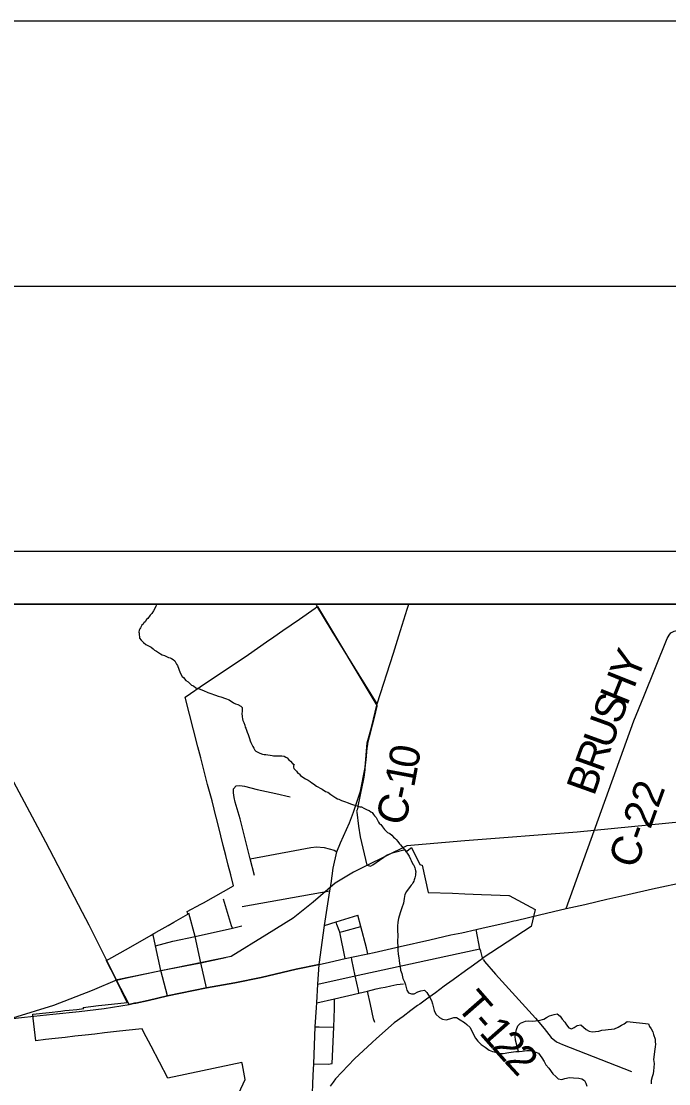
# Model space of a CAD drawing. Extents: x 0 to 34, y 0 to 22.
# Drawn here: x 7.241 to 8.463, y 19.995 to 22 of the extents above; entities that cross this region are included whole.
import ezdxf

# ---------------------------------------------------------------- set-up
doc = ezdxf.new("R2010")
doc.units = 0
for name, color, linetype in [('GM_X_City_Street', 7, 'Continuous'), ('GM_X_Corporation', 7, 'Continuous'), ('GM_X_County_Road', 7, 'Continuous'), ('GM_X_County_Road_Text', 7, 'Continuous'), ('GM_X_Minor_River', 7, 'Continuous'), ('GM_X_Rail_Line', 7, 'Continuous'), ('GM_X_State_Route', 7, 'Continuous'), ('GM_X_Township_Road', 7, 'Continuous'), ('GM_X_Township_Road_Text', 7, 'Continuous'), ('GM_X_US_Route', 7, 'Continuous'), ('SH_Border', 7, 'Continuous'), ('SH_Cut_Line', 7, 'Continuous'), ('SH_Data', 7, 'Continuous')]:
    doc.layers.add(name, color=color, linetype=linetype)

msp = doc.modelspace()

# ---------------------------------------------------------------- linework, layer by layer
at = {"layer": 'GM_X_City_Street'}
msp.add_line((7.6574, 20.3301), (7.823, 20.3596), dxfattribs=at)
for points in [[(7.6809, 20.3883), (7.6729, 20.4199), (7.6539, 20.4951), (7.6446, 20.5269), (7.6423, 20.5353), (7.6409, 20.5442), (7.6413, 20.5521), (7.6461, 20.5573), (7.6532, 20.5581), (7.6619, 20.5566), (7.6861, 20.5507), (7.7208, 20.5429), (7.7483, 20.5366)], [(7.8027, 20.2202), (7.8131, 20.2941), (7.823, 20.3596), (7.8252, 20.3734), (7.8296, 20.4023), (7.8364, 20.4327), (7.8431, 20.45), (7.8599, 20.4875), (7.8677, 20.5081)], [(7.6729, 20.4199), (7.7572, 20.4353), (7.7874, 20.4412), (7.7976, 20.4422), (7.8124, 20.441), (7.8312, 20.4363), (7.8364, 20.4327)], [(7.6394, 20.2892), (7.6377, 20.2935), (7.6221, 20.344)], [(7.5903, 20.1767), (7.5795, 20.2234), (7.5686, 20.2732), (7.5569, 20.3175)], [(7.8131, 20.2941), (7.835, 20.3011), (7.8757, 20.3133)], [(7.8949, 20.2406), (7.8923, 20.2521), (7.8816, 20.2923), (7.8757, 20.3133)], [(7.494, 20.2555), (7.5269, 20.2647), (7.5686, 20.2732), (7.6394, 20.2892), (7.6566, 20.2936)], [(7.8522, 20.2316), (7.842, 20.2815), (7.8365, 20.2961), (7.835, 20.3011)], [(7.842, 20.2815), (7.8497, 20.2831), (7.8816, 20.2923)], [(8.1133, 20.2293), (8.1114, 20.2331), (8.1096, 20.238), (8.1079, 20.2457), (8.1064, 20.2502), (8.099, 20.2864)], [(7.5168, 20.161), (7.5043, 20.2091), (7.494, 20.2555), (7.4895, 20.2767)], [(7.8004, 20.1832), (7.8711, 20.1989), (8.042, 20.2362), (8.1064, 20.2502)], [(7.4206, 20.1906), (7.4391, 20.1952), (7.5043, 20.2091), (7.5795, 20.2234), (7.626, 20.2334)], [(7.8711, 20.1989), (7.8648, 20.2291), (7.8641, 20.2344)], [(7.8779, 20.1662), (7.8772, 20.1716), (7.8711, 20.1989)], [(7.7984, 20.1484), (7.8319, 20.1558), (7.8779, 20.1662), (7.894, 20.17), (7.9105, 20.1743), (7.9191, 20.1761)], [(7.9078, 20.1109), (7.9057, 20.1182), (7.8998, 20.1448), (7.894, 20.17)], [(7.9191, 20.1761), (7.9276, 20.1779), (7.9382, 20.18), (7.9493, 20.1825), (7.9619, 20.1841)], [(7.8276, 20.0334), (7.8308, 20.102), (7.8318, 20.1375), (7.8319, 20.1558)], [(7.7952, 20.1028), (7.8031, 20.1027), (7.8308, 20.102)], [(7.793, 20.0332), (7.8198, 20.0322), (7.8276, 20.0334)]]:
    msp.add_lwpolyline(points, dxfattribs=at)
at = {"layer": 'GM_X_Corporation'}
for points in [[(8.9, 18.9286), (8.9, 20.9), (3.0971, 20.9)], [(7.6513, 19.9777), (7.6633, 20.0035), (7.658, 20.0314), (7.6571, 20.0357), (7.5828, 20.0199), (7.5175, 20.006), (7.4858, 20.0663), (7.4716, 20.0933), (7.4685, 20.0993), (7.4624, 20.0986), (7.426, 20.0945), (7.3977, 20.0913), (7.3792, 20.0892), (7.361, 20.0872), (7.342, 20.085), (7.3233, 20.0829), (7.3047, 20.0808), (7.2861, 20.0787), (7.2679, 20.0767), (7.2633, 20.1189), (7.2627, 20.1266), (7.2934, 20.1301), (7.3151, 20.1325), (7.3231, 20.1334), (7.3307, 20.1343), (7.3454, 20.1358), (7.3585, 20.1372), (7.3573, 20.1395), (7.3863, 20.1428), (7.3987, 20.1446), (7.4406, 20.149), (7.4188, 20.1929), (7.4104, 20.2106), (7.4013, 20.2276), (7.401, 20.2282), (7.4057, 20.2307), (7.4429, 20.2515), (7.4858, 20.276), (7.491, 20.2789), (7.4944, 20.2809), (7.4953, 20.2814), (7.5176, 20.2943), (7.5283, 20.3004), (7.5549, 20.3154), (7.5538, 20.3203), (7.5796, 20.3343), (7.5846, 20.3369), (7.6412, 20.3687), (7.6359, 20.3896), (7.6312, 20.4081), (7.6266, 20.4263), (7.6218, 20.4452), (7.6173, 20.4631), (7.6089, 20.4963), (7.6086, 20.4977), (7.6006, 20.5291), (7.5922, 20.5599), (7.5793, 20.6104), (7.5739, 20.6311), (7.5499, 20.7248), (7.5882, 20.7511), (7.6443, 20.7883), (7.6692, 20.8055), (7.7034, 20.8291), (7.7172, 20.8387), (7.734, 20.8503), (7.7656, 20.8722), (7.7954, 20.8928), (7.7956, 20.8929), (7.7987, 20.895), (7.7997, 20.8957), (7.912, 20.7088), (7.9119, 20.7084), (7.9118, 20.7082), (7.9118, 20.7079), (7.9117, 20.7076), (7.9117, 20.7075), (7.9116, 20.707), (7.9115, 20.707), (7.9114, 20.7065), (7.9114, 20.7064), (7.9113, 20.706), (7.9113, 20.7058), (7.9112, 20.7055), (7.9111, 20.7052), (7.9111, 20.705), (7.911, 20.7046), (7.9109, 20.7045), (7.9108, 20.704), (7.9107, 20.7036), (7.9107, 20.7034), (7.9106, 20.7031), (7.9105, 20.7028), (7.9105, 20.7026), (7.9104, 20.7022), (7.9103, 20.7021), (7.9102, 20.7016), (7.9102, 20.7016), (7.9101, 20.7011), (7.9101, 20.701), (7.91, 20.7006), (7.9099, 20.7004), (7.9099, 20.7002), (7.9098, 20.6998), (7.9097, 20.6997), (7.9096, 20.6992), (7.9095, 20.6987), (7.9094, 20.6982), (7.9094, 20.6981), (7.9093, 20.6977), (7.9092, 20.6975), (7.9092, 20.6972), (7.909, 20.6967), (7.9089, 20.6963), (7.9028, 20.6722), (7.8995, 20.6593), (7.8944, 20.6377), (7.8944, 20.6374), (7.8943, 20.6372), (7.8943, 20.637), (7.8943, 20.6367), (7.8942, 20.6365), (7.8942, 20.6362), (7.8941, 20.636), (7.8941, 20.6358), (7.894, 20.6355), (7.894, 20.6353), (7.8939, 20.635), (7.8939, 20.6348), (7.8939, 20.6346), (7.8938, 20.6343), (7.8938, 20.6341), (7.8937, 20.6338), (7.8937, 20.6336), (7.8936, 20.6333), (7.8936, 20.6331), (7.8936, 20.6329), (7.8935, 20.6326), (7.8935, 20.6324), (7.8934, 20.6321), (7.8934, 20.6319), (7.8934, 20.6317), (7.8933, 20.6314), (7.8933, 20.6312), (7.8933, 20.6309), (7.8932, 20.6307), (7.8932, 20.6304), (7.8932, 20.6302), (7.8931, 20.63), (7.8931, 20.6297), (7.8931, 20.6295), (7.893, 20.6292), (7.893, 20.629), (7.893, 20.6287), (7.8929, 20.6285), (7.8929, 20.6283), (7.8929, 20.628), (7.8928, 20.6278), (7.8928, 20.6275), (7.8928, 20.6273), (7.8928, 20.627), (7.8927, 20.6268), (7.8927, 20.6266), (7.8927, 20.6263), (7.8926, 20.6261), (7.8926, 20.6258), (7.8926, 20.6256), (7.8926, 20.6253), (7.8925, 20.6251), (7.8925, 20.6248), (7.8925, 20.6246), (7.8925, 20.6244), (7.8924, 20.6241), (7.8924, 20.6239), (7.8924, 20.6236), (7.8924, 20.6234), (7.8924, 20.6231), (7.8923, 20.6229), (7.8922, 20.6215), (7.8914, 20.6126), (7.8893, 20.5907), (7.8893, 20.5903), (7.8892, 20.5899), (7.8892, 20.5895), (7.8892, 20.5891), (7.8891, 20.5887), (7.8891, 20.5883), (7.889, 20.5879), (7.889, 20.5875), (7.8889, 20.5871), (7.8889, 20.5868), (7.8889, 20.5864), (7.8888, 20.586), (7.8888, 20.5856), (7.8887, 20.5852), (7.8887, 20.5848), (7.8886, 20.5844), (7.8886, 20.584), (7.8885, 20.5836), (7.8885, 20.5832), (7.8884, 20.5828), (7.8884, 20.5824), (7.8883, 20.582), (7.8883, 20.5816), (7.8882, 20.5812), (7.8881, 20.5808), (7.8881, 20.5804), (7.888, 20.58), (7.888, 20.5796), (7.8879, 20.5792), (7.8879, 20.5788), (7.8878, 20.5784), (7.8877, 20.578), (7.8877, 20.5776), (7.8876, 20.5772), (7.8876, 20.5768), (7.8875, 20.5764), (7.8874, 20.576), (7.8874, 20.5756), (7.8873, 20.5752), (7.8872, 20.5748), (7.8872, 20.5744), (7.8871, 20.574), (7.887, 20.5736), (7.887, 20.5733), (7.8869, 20.5729), (7.8868, 20.5725), (7.8868, 20.5721), (7.8867, 20.5717), (7.8866, 20.5713), (7.8865, 20.5709), (7.8865, 20.5705), (7.8864, 20.5701), (7.8863, 20.5697), (7.8862, 20.5693), (7.8862, 20.5689), (7.8861, 20.5685), (7.886, 20.5681), (7.8859, 20.5677), (7.8858, 20.5673), (7.8858, 20.5669), (7.8857, 20.5666), (7.8856, 20.5662), (7.8855, 20.5658), (7.8854, 20.5654), (7.8854, 20.565), (7.8853, 20.5646), (7.8852, 20.5642), (7.8851, 20.5638), (7.885, 20.5634), (7.8849, 20.563), (7.8848, 20.5626), (7.8848, 20.5622), (7.8847, 20.5618), (7.8846, 20.5615), (7.8845, 20.5611), (7.8844, 20.5607), (7.8843, 20.5603), (7.8842, 20.5599), (7.8841, 20.5595), (7.884, 20.5591), (7.8839, 20.5587), (7.8761, 20.5194), (7.8757, 20.5174), (7.8749, 20.5122), (7.8735, 20.5094), (7.8737, 20.5078), (7.8774, 20.4813), (7.8801, 20.4611), (7.8931, 20.4078), (7.8932, 20.4078), (7.9, 20.4058), (7.904, 20.4085), (7.9314, 20.4272), (7.9318, 20.4274), (7.9425, 20.4316), (7.9433, 20.4318), (7.965, 20.4376), (7.9666, 20.4329), (7.9774, 20.4409), (7.9928, 20.4093), (7.9968, 20.4079), (7.9971, 20.4078), (8.0085, 20.3563), (8.0548, 20.3547), (8.0775, 20.3538), (8.1093, 20.3527), (8.1278, 20.3521), (8.1444, 20.3515), (8.1611, 20.3508), (8.1613, 20.3508), (8.2108, 20.3239), (8.2029, 20.2922), (8.1125, 20.2328), (8.1102, 20.2311), (8.1081, 20.2295), (8.0896, 20.2161), (8.0834, 20.2116), (8.072, 20.2033), (8.0652, 20.1984), (8.0557, 20.1914), (8.0433, 20.1824), (8.039, 20.1793), (8.0222, 20.1671), (8.0056, 20.155), (7.9931, 20.1459), (7.9887, 20.1428), (7.976, 20.1336), (7.9611, 20.1224), (7.9443, 20.1101), (7.9112, 20.081), (7.9029, 20.0733), (7.8694, 20.0422), (7.8338, 20.0045), (7.8293, 19.9984), (7.8236, 19.9907)]]:
    msp.add_lwpolyline(points, dxfattribs=at)
at = {"layer": 'GM_X_County_Road'}
for points in [[(7.9121, 20.7122), (7.9433, 20.8079), (7.9531, 20.8407), (7.9688, 20.8907), (7.972, 20.9)], [(8.269, 20.3262), (8.3971, 20.68), (8.4155, 20.7258), (8.4599, 20.8356), (8.4634, 20.8415), (8.4669, 20.846), (8.4731, 20.8493), (8.4837, 20.8517), (8.4996, 20.8521), (8.5272, 20.8519), (8.5461, 20.8511), (8.5563, 20.8517), (8.5643, 20.8526), (8.5738, 20.8566), (8.583, 20.8632), (8.5919, 20.8687), (8.6071, 20.8752), (8.6469, 20.8937), (8.6571, 20.9)], [(7.8677, 20.5081), (7.8808, 20.5476), (7.8894, 20.5919), (7.8937, 20.6386), (7.9017, 20.6676), (7.9121, 20.7122)]]:
    msp.add_lwpolyline(points, dxfattribs=at)
at = {"layer": 'GM_X_Minor_River'}
for points in [[(7.4969, 20.9), (7.4952, 20.8981), (7.4948, 20.8958), (7.49, 20.8876), (7.4872, 20.8827), (7.4841, 20.8798), (7.4794, 20.8734), (7.4767, 20.8712), (7.4743, 20.8671), (7.472, 20.8649), (7.4704, 20.8627), (7.4684, 20.8604), (7.4672, 20.8582), (7.4657, 20.8556), (7.4641, 20.8534), (7.4633, 20.8511), (7.4628, 20.8477), (7.4631, 20.8454), (7.4634, 20.8416), (7.4637, 20.8393), (7.464, 20.8363), (7.4666, 20.8324), (7.471, 20.8278), (7.4755, 20.8242), (7.4785, 20.823), (7.4819, 20.821), (7.4856, 20.819), (7.4897, 20.8159), (7.4923, 20.8135), (7.4961, 20.8115), (7.5031, 20.8064), (7.5065, 20.8044), (7.5107, 20.8032), (7.5186, 20.7999), (7.5216, 20.7987), (7.5242, 20.7979), (7.5276, 20.7959), (7.5302, 20.7932), (7.5338, 20.787), (7.5356, 20.7843), (7.5406, 20.7709), (7.5442, 20.764), (7.5468, 20.762), (7.5512, 20.7562), (7.5557, 20.7538), (7.5617, 20.7476), (7.5658, 20.746), (7.5699, 20.7425), (7.5763, 20.7404), (7.5846, 20.7375), (7.5928, 20.7339), (7.5966, 20.7323), (7.6075, 20.7286), (7.6124, 20.7269), (7.6173, 20.7257), (7.6263, 20.722), (7.6331, 20.7199), (7.6413, 20.7144), (7.6451, 20.7124), (7.6492, 20.7108)], [(7.6492, 20.7108), (7.6552, 20.7076), (7.6574, 20.7053), (7.6576, 20.6969), (7.6572, 20.6946), (7.6574, 20.6874), (7.6584, 20.6836), (7.6587, 20.6809), (7.6605, 20.6767), (7.6627, 20.6717), (7.6633, 20.6683), (7.6644, 20.666), (7.6669, 20.6587), (7.6691, 20.6545), (7.6694, 20.6522), (7.6715, 20.6465), (7.6726, 20.6426), (7.674, 20.6392), (7.6776, 20.6319), (7.6798, 20.6288), (7.6816, 20.6249), (7.6834, 20.6226), (7.6906, 20.619), (7.6958, 20.6174), (7.6989, 20.6169), (7.7023, 20.6164), (7.7061, 20.616), (7.7106, 20.6151), (7.7144, 20.6146), (7.7167, 20.6142), (7.7193, 20.6141), (7.7227, 20.6144), (7.7326, 20.6141), (7.7371, 20.6133), (7.7401, 20.6117), (7.7424, 20.6101), (7.7457, 20.6066), (7.7487, 20.6038), (7.7524, 20.5996), (7.7554, 20.5976), (7.7545, 20.595), (7.7545, 20.5927), (7.7552, 20.59), (7.7574, 20.5877), (7.76, 20.5853), (7.7625, 20.5815), (7.7648, 20.5803), (7.7677, 20.5768), (7.7719, 20.574), (7.7771, 20.5705), (7.7823, 20.5684), (7.7861, 20.5657), (7.789, 20.5629), (7.7924, 20.5613), (7.798, 20.557), (7.8003, 20.5558), (7.8047, 20.5531), (7.8085, 20.5514), (7.8148, 20.5471), (7.819, 20.5455), (7.8246, 20.5412), (7.8287, 20.5384), (7.8343, 20.5348), (7.8373, 20.5332), (7.8399, 20.5324), (7.8452, 20.5296), (7.8508, 20.5279), (7.8576, 20.5255), (7.8617, 20.5235), (7.8659, 20.5226), (7.8719, 20.5206), (7.8749, 20.5197), (7.8798, 20.5181), (7.8825, 20.5176), (7.887, 20.5156), (7.89, 20.5144), (7.8937, 20.5124), (7.8975, 20.5108), (7.9001, 20.5084), (7.9027, 20.5069), (7.9057, 20.5037), (7.9071, 20.5007), (7.9104, 20.4979), (7.9148, 20.4891), (7.917, 20.486), (7.9192, 20.4844), (7.9222, 20.4802), (7.924, 20.4775), (7.9262, 20.4751), (7.9321, 20.4697), (7.9363, 20.4673), (7.94, 20.4645), (7.9429, 20.4607), (7.9459, 20.4587), (7.9481, 20.4563), (7.9511, 20.4525), (7.9548, 20.4482), (7.9566, 20.4459), (7.9588, 20.4432), (7.9658, 20.4346), (7.9702, 20.4284)], [(7.9702, 20.4284), (7.9728, 20.4246), (7.9753, 20.4192), (7.9764, 20.4165), (7.9796, 20.41), (7.9815, 20.4077), (7.9832, 20.4031), (7.9843, 20.4004), (7.985, 20.3973), (7.9853, 20.395), (7.9849, 20.3924), (7.9848, 20.389), (7.9843, 20.3867), (7.9835, 20.3837), (7.9823, 20.3803), (7.9815, 20.3777), (7.9795, 20.3747), (7.9783, 20.3721), (7.9767, 20.3699), (7.9747, 20.3676)], [(7.9747, 20.3676), (7.9674, 20.3584), (7.9646, 20.3523), (7.9633, 20.3451), (7.962, 20.336), (7.9588, 20.3273), (7.9556, 20.3179), (7.9524, 20.3069), (7.9512, 20.3001), (7.9507, 20.2925), (7.9505, 20.2849), (7.9511, 20.2746), (7.9509, 20.2643), (7.9511, 20.2525), (7.9514, 20.2476), (7.952, 20.24), (7.9531, 20.2331), (7.9537, 20.2278), (7.9548, 20.2224), (7.9555, 20.2167), (7.9561, 20.2098), (7.9587, 20.2037), (7.9608, 20.1942), (7.9641, 20.1876), (7.9659, 20.1819), (7.9684, 20.1723), (7.9717, 20.167), (7.9774, 20.1653), (7.9823, 20.1649), (7.9892, 20.1689), (7.9946, 20.1707), (8.0015, 20.1718), (8.0063, 20.1679), (8.0111, 20.1594), (8.0148, 20.1525), (8.0166, 20.1464), (8.0184, 20.1384), (8.0198, 20.1334), (8.0231, 20.1269), (8.0302, 20.1203), (8.0359, 20.1175), (8.0423, 20.1159), (8.0492, 20.1181), (8.0569, 20.1206), (8.0622, 20.1205), (8.0693, 20.1158), (8.0769, 20.1111), (8.0817, 20.1072), (8.0877, 20.1018), (8.0929, 20.091), (8.098, 20.0814), (8.1025, 20.076), (8.1088, 20.0695), (8.116, 20.0644), (8.1239, 20.0586), (8.1303, 20.0562), (8.136, 20.0549), (8.1428, 20.0525), (8.15, 20.0524), (8.1607, 20.0545), (8.174, 20.0562), (8.1805, 20.0564), (8.1858, 20.0571), (8.195, 20.0581), (8.1999, 20.058), (8.2048, 20.0575), (8.2101, 20.0555), (8.2169, 20.0531), (8.2232, 20.0446), (8.2273, 20.0377), (8.231, 20.0312), (8.2362, 20.0246), (8.2436, 20.0139), (8.2493, 20.0092), (8.2541, 20.0049), (8.2606, 20.0033), (8.2663, 20.0055), (8.2751, 20.0072), (8.2831, 20.0067), (8.2929, 20.0058), (8.2986, 20.0045), (8.3039, 20.0014), (8.3061, 19.9964), (8.3079, 19.991)], [(8.1789, 20.0564), (8.1732, 20.0775), (8.1726, 20.0851), (8.1739, 20.0919), (8.1755, 20.0976), (8.1779, 20.1048), (8.1829, 20.1096), (8.1921, 20.1133), (8.1986, 20.1139), (8.2058, 20.1138), (8.2115, 20.1141), (8.2172, 20.1147), (8.2271, 20.1172), (8.2321, 20.1202), (8.2375, 20.1235), (8.2463, 20.1264), (8.252, 20.1271), (8.2576, 20.1232), (8.2613, 20.1174), (8.2666, 20.1116), (8.2699, 20.1066), (8.2744, 20.1012), (8.2793, 20.0992), (8.2843, 20.1018), (8.29, 20.1055), (8.2969, 20.1069), (8.3018, 20.1022), (8.307, 20.0976), (8.3127, 20.0944), (8.318, 20.0936), (8.3244, 20.0938), (8.3305, 20.0949), (8.3363, 20.0963), (8.3431, 20.0969), (8.3485, 20.0976), (8.3549, 20.0982), (8.3606, 20.0989), (8.3675, 20.1022), (8.3733, 20.1059), (8.3783, 20.1085), (8.3841, 20.1126)], [(8.3841, 20.1126), (8.4244, 20.1083), (8.4266, 20.1037), (8.4295, 20.099), (8.4328, 20.0936), (8.4342, 20.0886), (8.437, 20.0794), (8.4372, 20.0744), (8.4375, 20.0699), (8.4373, 20.0653), (8.4359, 20.0562), (8.435, 20.0505), (8.434, 20.0414), (8.4349, 20.0338), (8.4347, 20.0258), (8.4342, 20.0201), (8.4332, 20.0144), (8.4316, 20.0083), (8.4298, 20.0015), (8.4297, 19.9951)]]:
    msp.add_lwpolyline(points, dxfattribs=at)
at = {"layer": 'GM_X_Rail_Line'}
msp.add_lwpolyline([(8.9, 20.5317), (8.865, 20.5331), (8.6616, 20.5066), (8.2899, 20.47), (8.0777, 20.4538), (7.9686, 20.4444), (7.8915, 20.4068), (7.8679, 20.3946), (7.8333, 20.3737), (7.7918, 20.3381), (7.7538, 20.3081), (7.7039, 20.2773), (7.6367, 20.2356), (7.4218, 20.1917), (7.3745, 20.1714), (7.3015, 20.143), (7.2242, 20.1194), (6.8196, 20.081), (6.5058, 20.0545), (6.3266, 19.9988), (6.3068, 19.9813)], dxfattribs=at)
at = {"layer": 'GM_X_State_Route'}
for p, q in [((7.8004, 20.1832), (7.8027, 20.2202)), ((7.5903, 20.1767), (7.5168, 20.161)), ((7.7984, 20.1484), (7.8004, 20.1832)), ((7.4545, 20.1472), (7.4442, 20.1448)), ((7.7978, 20.1393), (7.7984, 20.1484)), ((7.7952, 20.1028), (7.7978, 20.1393)), ((7.793, 20.0332), (7.7952, 20.1028))]:
    msp.add_line(p, q, dxfattribs=at)
for points in [[(7.3563, 20.3183), (7.2869, 20.4512), (7.2163, 20.5836), (7.1774, 20.6568), (7.1438, 20.7179), (7.1209, 20.7646), (7.0934, 20.8162), (7.0666, 20.8644), (7.0484, 20.9)], [(7.4442, 20.1448), (7.4206, 20.1906), (7.4025, 20.2269), (7.3687, 20.2945), (7.3563, 20.3183)], [(7.8027, 20.2202), (7.7596, 20.2117), (7.6932, 20.1961), (7.6439, 20.1861), (7.5903, 20.1767)], [(7.5168, 20.161), (7.4803, 20.1524), (7.4566, 20.1477), (7.4545, 20.1472)], [(7.7882, 19.9307), (7.7884, 19.938), (7.7894, 19.9612), (7.7917, 20.0117), (7.793, 20.0332)]]:
    msp.add_lwpolyline(points, dxfattribs=at)
at = {"layer": 'GM_X_Township_Road'}
for points in [[(7.9121, 20.7122), (7.8784, 20.7669), (7.8273, 20.8496), (7.7986, 20.8973), (7.7971, 20.9)], [(8.1133, 20.2293), (8.115, 20.2261), (8.1355, 20.2025), (8.2115, 20.1191), (8.2275, 20.0994), (8.2409, 20.083), (8.2508, 20.0744), (8.2622, 20.0693), (8.3926, 20.0184)]]:
    msp.add_lwpolyline(points, dxfattribs=at)
at = {"layer": 'GM_X_US_Route'}
for p, q in [((7.5168, 20.161), (7.5903, 20.1767)), ((7.4442, 20.1448), (7.4545, 20.1472))]:
    msp.add_line(p, q, dxfattribs=at)
for points in [[(8.3276, 20.3392), (8.3459, 20.3436), (8.3856, 20.3526), (8.4323, 20.3633), (8.4969, 20.3771), (8.5599, 20.3919), (8.6133, 20.4038), (8.6745, 20.4178), (8.7359, 20.4325), (8.8125, 20.4497), (8.8623, 20.461), (8.9, 20.4695)], [(8.2452, 20.3204), (8.269, 20.3262), (8.3045, 20.3336), (8.3276, 20.3392)], [(8.1749, 20.3036), (8.2186, 20.314), (8.2452, 20.3204)], [(7.8027, 20.2202), (7.8222, 20.2248), (7.8522, 20.2316), (7.8584, 20.2333), (7.8641, 20.2344), (7.8949, 20.2406), (7.9069, 20.2428), (7.9555, 20.2547), (8.0118, 20.2669), (8.0516, 20.2762), (8.0722, 20.2799), (8.099, 20.2864), (8.1124, 20.2895), (8.1551, 20.2988), (8.1702, 20.3025), (8.1749, 20.3036)], [(7.5903, 20.1767), (7.6439, 20.1861), (7.6932, 20.1961), (7.7596, 20.2117), (7.8027, 20.2202)], [(7.4545, 20.1472), (7.4566, 20.1477), (7.4803, 20.1524), (7.5168, 20.161)], [(7.2642, 20.1229), (7.3002, 20.127), (7.35, 20.132), (7.3969, 20.1376), (7.4442, 20.1448)], [(6.367, 20.0102), (6.3866, 20.0168), (6.4322, 20.031), (6.4735, 20.043), (6.4915, 20.0472), (6.5127, 20.0525), (6.537, 20.0565), (6.5826, 20.0599), (6.6371, 20.0636), (6.6764, 20.0684), (6.7225, 20.0723), (6.7715, 20.0765), (6.8227, 20.0797), (6.8858, 20.086), (6.9315, 20.0892), (6.9813, 20.0928), (7.1812, 20.1136), (7.2412, 20.1203), (7.2642, 20.1229)]]:
    msp.add_lwpolyline(points, dxfattribs=at)
at = {"layer": 'SH_Border'}
msp.add_lwpolyline([(1.5, 21.5), (33.5, 21.5), (33.5, 0.5), (1.5, 0.5)], close=True, dxfattribs=at)
at = {"layer": 'SH_Cut_Line'}
msp.add_lwpolyline([(0, 0), (34, 0), (34, 22), (0, 22)], close=True, dxfattribs=at)
at = {"layer": 'SH_Data'}
for p, q in [((2, 21), (9, 21)), ((2.1, 20.9), (8.9, 20.9))]:
    msp.add_line(p, q, dxfattribs=at)

# ---------------------------------------------------------------- texts
at = {"layer": 'GM_X_County_Road_Text'}
for s, height, rotation, p in [('Y', 0.0568, 67.9815, (8.4024, 20.7532)), ('H', 0.0568, 68.1499, (8.3838, 20.7068)), ('S', 0.0568, 69.0836, (8.3702, 20.6712)), ('U', 0.0568, 70.0293, (8.3533, 20.6245)), ('0', 0.0568, 79.9003, (7.9884, 20.5878)), ('R', 0.0568, 70.248, (8.3375, 20.5806)), ('1', 0.0568, 79.3459, (7.9819, 20.5528)), ('B', 0.0568, 70.248, (8.3217, 20.5367)), ('-', 0.0568, 77.9796, (7.9767, 20.5286)), ('C-22', 0.05682, 70.0466, (8.4006, 20.3988)), ('C', 0.0568, 73.6798, (7.9625, 20.4793))]:
    msp.add_text(s, height=height, rotation=rotation, dxfattribs=at).set_placement(p)
at = {"layer": 'GM_X_Township_Road_Text'}
for s, rotation, p in [('T', 311.2214, (8.0597, 20.1406)), ('-', 311.2436, (8.0877, 20.1086)), ('1', 311.3574, (8.1032, 20.0909)), ('2', 311.7259, (8.1265, 20.0644)), ('2', 312.7272, (8.1506, 20.0374))]:
    msp.add_text(s, height=0.0568, rotation=rotation, dxfattribs=at).set_placement(p)

doc.saveas('drawing.dxf')
